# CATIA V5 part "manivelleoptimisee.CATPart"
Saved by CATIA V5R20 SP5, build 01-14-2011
Part number: manivelle
Publications: "epaisseur", "diamètre manivelle", "longueur manivelle", "petit entraxe", "diamètre pivot"
Bounding box of the stored display mesh (mm): x -5 to 25, y -10 to 110, z -10 to 10
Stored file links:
  C:\Documents and Settings\pcochet\Bureau\PROJ IAO\manivelleopt2.CATPart
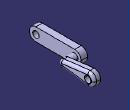
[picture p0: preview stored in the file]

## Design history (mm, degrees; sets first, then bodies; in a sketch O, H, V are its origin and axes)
Parameters
  epaisseur = 5 mm
  `diamètre manivelle` = 20 mm
  `longueur manivelle` = 100 mm
  `petit entraxe` = 40 mm
  `diamètre pivot` = 10 mm
Body1 (main body)
  Point1: (0, 0, 0)
  Point2: (0, 60 {= `longueur manivelle` -`petit entraxe`}, 0)
  Point3: (20 {= epaisseur *4}, 100 {= `longueur manivelle`}, 0)
  Plane1: type OffsetPt, RefPlane yz-plane, RefPoint Point3
  Point4: (20 {= epaisseur *4}, 60 {= `longueur manivelle` -`petit entraxe`}, 0)
  Line1: type PtPt, FirstPoint Point2, SecondPoint Point4
  Line2: type PtPt, FirstPoint Point1, SecondPoint Point2
  Line3: type PtPt, FirstPoint Point4, SecondPoint Point3
  Sketch1 on xy-plane, origin (0, 0, 0), H (1, 0, 0), V (0, 1, 0)
    line L1 (-5, -10) -> (-5, 70)
    line L2 (-5, 70) -> (15, 70)
    line L3 (15, 70) -> (15, 110)
    line L4 (15, 110) -> (25, 110)
    line L5 (25, 110) -> (25, 50)
    line L6 (25, 50) -> (5, 50)
    line L7 (5, 50) -> (5, -10)
    line L8 (5, -10) -> (-5, -10)
    reference projected line E1 (0, 0) -> (0, 60) from Line2
    reference projected line E2 (0, 60) -> (10, 60) from Line1
    reference projected line E3 (20, 60.6226) -> (20, 100.6226) from Line3
    reference projected point E4 (0, 0) from Point1
    reference projected point E5 (20, 100) from Point3
    distance L7 L1 = 10 {= epaisseur *2}
    distance L3 L5 = 10 {= epaisseur *2}
    distance L2 L6 = 20
    distance E4 L8 = 10 {= `diamètre manivelle` /2}
    distance L4 E5 = 10 {= `diamètre manivelle` /2}
    vertical: L1 V, L3 V, L5 V
    horizontal: L2 H, L4 H, L6 H, L8 H
    parallelism: L7 L5
    symmetry: L1 L7 E1, L6 L2 E2, L3 L5 E3
  Pad1: profile Sketch1, direction (0, 0, 1), length 10 {= `diamètre manivelle` /2}, mirrored extent
  Sketch2 on face of Pad1 from Sketch1.L5, origin (25, 0, 0), H (0, 1, 0), V (0, 0, 1)
    circle A1 centre (100, 0) radius 5
    point P1 (100, 0)
    circle A2 centre (0, 0) radius 5
    point P2 (0, 0)
    reference projected point E1 (100, 0) from Point3
    reference projected point E2 (0, 0) from Point1
    radius A2 = 5 {= `diamètre pivot` /2}
    radius A1 = 5 {= `diamètre pivot` /2}
    coincidence: P1 E1, P2 E2
  Pocket1: profile Sketch2, direction (-1, 0, 0), through (limit type 3)
  Point5: type Between, FirstPoint Point2, SecondPoint Point4, Ratio 0.5
  Plane2: type OffsetPt, RefPlane yz-plane, RefPoint Point5
  Sketch3 on Plane2, origin (10, 0, 0), H (0, 1, 0), V (0, 0, 1)
    circle A1 centre (60, 0) radius 5
    point P1 (60, 0)
    reference projected point E1 (60, 0) from Point5
    line L1 (50, 10) -> (70, 10)
    line L2 (70, 10) -> (70, -10)
    line L3 (70, -10) -> (50, -10)
    line L4 (50, -10) -> (50, 10)
    reference projected line E2 (50, 10) -> (110, 10) from edge [face of Pad1 from Sketch1.L5 | end face of Pad1]
    reference projected line E3 (50, -10) -> (50, 10) from edge [face of Pad1 from Sketch1.L5 | face of Pad1 from Sketch1.L6]
    distance L1 L3 = 20 {= `diamètre manivelle`}
    distance L2 L4 = 20 {= `diamètre manivelle`}
    radius A1 = 5 {= `diamètre pivot` /2}
    coincidence: P1 H, P1 E1, L1 E2, L4 E3
    horizontal: L1 H, L3 H
    vertical: L2 V, L4 V
  Pocket2: profile Sketch3, direction (-1, 0, 0), length 5 {= epaisseur}, mirrored extent
  Sketch4 on face of Pad1 from Sketch1.L5, origin (25, 0, 0), H (0, 1, 0), V (0, 0, 1)
    arc A1 centre (60, 0) radius 5 from (59.3845, 4.962) to (59.3845, -4.962) ccw
    point P1 (60, 0)
    reference projected point E1 (60, 0) from axis of face of Pocket2 from Sketch3.A1
    line L1 (50, 10) -> (50, -10)
    line L2 (50, -10) -> (100, -10)
    point P4 (100, -10)
    line L3 (50, 10) -> (100, 10)
    point P5 (100, 10)
    reference projected line E2 (50, 10) -> (110, 10) from edge [face of Pad1 from Sketch1.L5 | end face of Pad1]
    reference projected line E3 (50, -10) -> (50, 10) from edge [face of Pad1 from Sketch1.L5 | face of Pad1 from Sketch1.L6]
    reference projected line E4 (50, -10) -> (110, -10) from edge [start face of Pad1 | face of Pad1 from Sketch1.L5]
    line L4 (100, 10) -> (59.3845, 4.962)
    line L5 (100, -10) -> (59.3845, -4.962)
    reference projected point E5 (110, -10) from vertex [face of Pad1 from Sketch1.L4 | start face of Pad1 | face of Pad1 from Sketch1.L5]
    reference projected point E6 (110, 10) from vertex [face of Pad1 from Sketch1.L4 | end face of Pad1 | face of Pad1 from Sketch1.L5]
    radius A1 = 5
    distance P4 E5 = 10
    distance P5 E6 = 10
    coincidence: P1 H, L3 E2, L1 E3, L2 E4
    concentricity: A1 E1
    vertical: L1 V
    tangency: L4 A1, L5 A1
  Pocket3: profile Sketch4, direction (-1, 0, 0), through (limit type 6)
  Fillet1: radius 10, on edge [face of Pad1 from Sketch1.L4 | end face of Pad1]; edge [start face of Pad1 | face of Pad1 from Sketch1.L4]; edge [start face of Pad1 | face of Pad1 from Sketch1.L2]; edge [face of Pad1 from Sketch1.L2 | end face of Pad1]; edge [face of Pad1 from Sketch1.L8 | end face of Pad1]; edge [start face of Pad1 | face of Pad1 from Sketch1.L8]
  Fillet2: radius 4, on edge [face of Pad1 from Sketch1.L5 | face of Pocket3]; edge [face of Pad1 from Sketch1.L5 | face of Pocket3 from Sketch4.L5]; edge [face of Pad1 from Sketch1.L5 | face of Pocket3 from Sketch4.L4]; edge [face of Pad1 from Sketch1.L5 | face of Fillet1]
